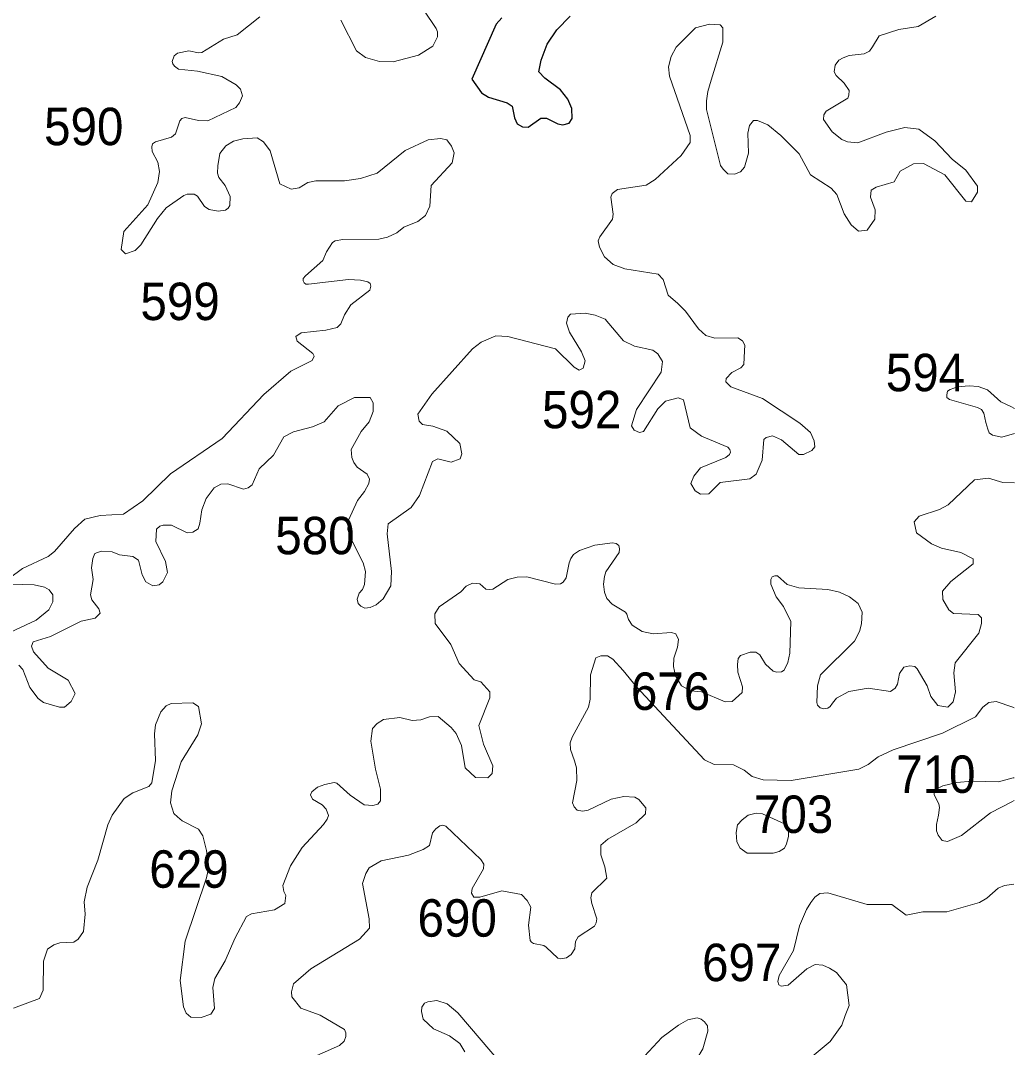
# Model space of a CAD drawing. Extents: x 499.9 to 555.3, y 9281.5 to 9336.8.
# Drawn here: x 551.055 to 555.305, y 9298.961 to 9303.351 of the extents above; entities that cross this region are included whole.
import ezdxf

# ---------------------------------------------------------------- set-up
doc = ezdxf.new("R2010")
doc.units = 0
doc.header["$LTSCALE"] = 0.064
doc.layers.add('1', color=7, linetype='Continuous', lineweight=25)
doc.layers.add('2', color=7, linetype='Continuous', lineweight=13)
doc.layers.add('21', color=7, linetype='Continuous')

msp = doc.modelspace()

# ---------------------------------------------------------------- linework, layer by layer
at = {"layer": '1'}
msp.add_lwpolyline([(553.1127, 9303.3619), (553.0892, 9303.3349), (552.9847, 9303.1), (553.0258, 9303.0418), (553.0556, 9303.023), (553.1358, 9302.9983), (553.157, 9302.9843), (553.1674, 9302.9346), (553.1789, 9302.9097), (553.2009, 9302.8966), (553.2251, 9302.8953), (553.2802, 9302.9335), (553.3035, 9302.9334), (553.3525, 9302.9085), (553.3743, 9302.9054), (553.4003, 9302.9116), (553.4136, 9302.9317), (553.4126, 9302.975), (553.3955, 9303.014), (553.3638, 9303.0545), (553.297, 9303.1037), (553.2717, 9303.1316), (553.2807, 9303.1811), (553.3073, 9303.2503), (553.3485, 9303.3108), (553.4057, 9303.3695)], dxfattribs=at)
at = {"layer": '2'}
for points in [[(552.4252, 9303.3521), (552.4919, 9303.2206), (552.5305, 9303.1932), (552.59, 9303.1751), (552.649, 9303.1742), (552.7564, 9303.2028), (552.8183, 9303.2409), (552.8376, 9303.281), (552.8381, 9303.3017), (552.8326, 9303.317), (552.7796, 9303.3945)], [(554.9685, 9303.3699), (554.8929, 9303.3257), (554.8109, 9303.312), (554.7269, 9303.285), (554.698, 9303.2378), (554.6844, 9303.2191), (554.6621, 9303.208), (554.5973, 9303.2017), (554.5726, 9303.1919), (554.5534, 9303.1812), (554.5374, 9303.1604), (554.5345, 9303.1311), (554.5427, 9303.1161), (554.5769, 9303.0831), (554.5973, 9303.0517), (554.5972, 9303.0309), (554.5927, 9303.0191), (554.4996, 9302.963), (554.4896, 9302.948), (554.4883, 9302.9281), (554.5256, 9302.8743), (554.5662, 9302.8415), (554.5907, 9302.8317), (554.6351, 9302.8273), (554.7555, 9302.8731), (554.8365, 9302.8935), (554.8954, 9302.8865), (554.9639, 9302.8365), (555.0382, 9302.7575), (555.0965, 9302.7116), (555.1468, 9302.6432), (555.1467, 9302.617), (555.1206, 9302.5755), (555.0967, 9302.5782), (555.0077, 9302.6904), (554.9153, 9302.7389), (554.8733, 9302.7376), (554.8166, 9302.7063), (554.7901, 9302.6617), (554.7134, 9302.6381), (554.6925, 9302.6251), (554.6887, 9302.5954), (554.7089, 9302.5411), (554.7071, 9302.5011), (554.6744, 9302.4551), (554.6378, 9302.4502), (554.6064, 9302.4769), (554.5772, 9302.5247), (554.5452, 9302.6072), (554.5217, 9302.634), (554.4331, 9302.691), (554.3841, 9302.7808), (554.3065, 9302.8587), (554.2509, 9302.9048), (554.2065, 9302.924), (554.1885, 9302.9233), (554.1713, 9302.9025), (554.1651, 9302.8691), (554.1681, 9302.7832), (554.1511, 9302.7233), (554.1327, 9302.7044), (554.1084, 9302.6943), (554.0795, 9302.6959)], [(552.8771, 9302.8409), (552.8503, 9302.8459), (552.7978, 9302.8411), (552.6992, 9302.7951), (552.5799, 9302.6986), (552.5081, 9302.6758), (552.4399, 9302.6656), (552.3172, 9302.6656), (552.2829, 9302.6583), (552.2471, 9302.6362), (552.2122, 9302.6299), (552.1637, 9302.6519), (552.1219, 9302.7934), (552.094, 9302.8315), (552.0673, 9302.8492), (552.0052, 9302.8445), (551.965, 9302.8343), (551.9325, 9302.8145), (551.9067, 9302.7822), (551.8981, 9302.7302), (551.8972, 9302.6981), (551.9028, 9302.6791), (551.9307, 9302.6448), (551.9509, 9302.5978), (551.9507, 9302.5598), (551.9436, 9302.5479), (551.9308, 9302.5394), (551.9008, 9302.5356), (551.8621, 9302.5424), (551.8423, 9302.5554), (551.8117, 9302.5996), (551.7972, 9302.6083), (551.7682, 9302.6084), (551.7531, 9302.6021), (551.6785, 9302.5495), (551.6403, 9302.5047), (551.5701, 9302.3924), (551.5452, 9302.3672), (551.5034, 9302.3528), (551.4854, 9302.3714), (551.4963, 9302.4495), (551.5988, 9302.5622), (551.642, 9302.6576), (551.65, 9302.706), (551.6426, 9302.7452), (551.6185, 9302.7913), (551.6171, 9302.8105), (551.6192, 9302.824), (551.6316, 9302.8324), (551.7001, 9302.8524), (551.7179, 9302.8666), (551.7363, 9302.9213), (551.7449, 9302.9312), (551.7591, 9302.9362), (551.8159, 9302.9227), (551.8564, 9302.9213), (551.9752, 9302.9791), (551.9912, 9302.9993), (552.0046, 9303.0293), (551.9958, 9303.057), (551.977, 9303.0763), (551.9161, 9303.1117), (551.8116, 9303.1335), (551.7309, 9303.1428), (551.7135, 9303.1559), (551.7066, 9303.1655), (551.7032, 9303.176), (551.7122, 9303.2003), (551.7261, 9303.2106), (551.7753, 9303.2215), (551.8154, 9303.2126), (551.8308, 9303.2143), (551.9225, 9303.2709), (551.9813, 9303.2897), (552.0779, 9303.366)], [(553.9937, 9303.0466), (554.0076, 9303.0951), (554.0578, 9303.2582), (554.0583, 9303.3196), (554.0459, 9303.3324), (554.0013, 9303.3345), (553.9412, 9303.3189), (553.859, 9303.2369), (553.8372, 9303.1962), (553.8262, 9303.1524), (553.8292, 9303.1128), (553.9178, 9302.8596), (553.9175, 9302.8289), (553.8794, 9302.7739), (553.7688, 9302.6707), (553.7296, 9302.6471), (553.6072, 9302.628), (553.5841, 9302.6113), (553.5791, 9302.595), (553.5892, 9302.5236), (553.5866, 9302.5018), (553.5316, 9302.4258), (553.5253, 9302.4094), (553.5301, 9302.3813), (553.5519, 9302.3407), (553.5895, 9302.3079), (553.6382, 9302.2891), (553.7818, 9302.2661), (553.8026, 9302.2436), (553.8238, 9302.176), (553.8658, 9302.1411), (553.898, 9302.1085), (553.9544, 9302.0332), (553.9847, 9302.0047), (554.0241, 9301.9932), (554.1225, 9301.9944), (554.1422, 9301.9818), (554.1516, 9301.9632), (554.1507, 9301.9389), (554.148, 9301.8805), (554.1341, 9301.8657), (554.096, 9301.8459), (554.0714, 9301.8209), (554.07, 9301.8067), (554.0922, 9301.7854), (554.227, 9301.7351), (554.3872, 9301.63), (554.432, 9301.5893), (554.4484, 9301.5536), (554.4511, 9301.5279), (554.4386, 9301.5124), (554.4028, 9301.4953), (554.3831, 9301.4951), (554.3081, 9301.5576), (554.2707, 9301.576), (554.2428, 9301.5685), (554.2335, 9301.5592), (554.2255, 9301.472), (554.2005, 9301.4115), (554.1727, 9301.3912), (554.0463, 9301.3755), (553.9976, 9301.328), (553.9623, 9301.3266), (553.9402, 9301.3397), (553.9217, 9301.3722), (553.9342, 9301.4025), (553.9618, 9301.4391), (554.0703, 9301.4834), (554.0859, 9301.4951), (554.0912, 9301.5056), (554.088, 9301.5172), (554.0798, 9301.5268), (553.966, 9301.5737), (553.9181, 9301.6103), (553.8893, 9301.7286), (553.8666, 9301.738), (553.8124, 9301.7241), (553.7793, 9301.6915), (553.7184, 9301.5944), (553.7011, 9301.5902), (553.6781, 9301.5993), (553.667, 9301.6178), (553.6893, 9301.6875), (553.7938, 9301.8477), (553.8, 9301.8931), (553.7806, 9301.9262), (553.7582, 9301.9421), (553.6796, 9301.9581), (553.6336, 9301.9809), (553.5542, 9302.0736), (553.5116, 9302.0913), (553.4687, 9302.0996), (553.4059, 9302.0961), (553.3946, 9302.0829), (553.39, 9302.0574)], [(554.0795, 9302.6959), (554.0597, 9302.7146), (554.0484, 9302.7314), (553.9883, 9302.971), (553.9887, 9303.0069), (553.9937, 9303.0466)], [(552.8055, 9302.5565), (552.8108, 9302.6455), (552.9003, 9302.742), (552.9089, 9302.7855), (552.8984, 9302.8143), (552.8771, 9302.8409)], [(551.0074, 9300.9675), (551.0631, 9301.0078), (551.1737, 9301.06), (551.2006, 9301.0807), (551.2855, 9301.1794), (551.3295, 9301.2197), (551.3952, 9301.2348), (551.4961, 9301.24), (551.5778, 9301.298), (551.6965, 9301.4136), (551.9169, 9301.5636), (552.096, 9301.7526), (552.2106, 9301.8513), (552.3021, 9301.8972), (552.3104, 9301.9166), (552.3046, 9301.9272), (552.2372, 9301.9795), (552.2322, 9301.9996), (552.2551, 9302.0151), (552.3602, 9302.0268), (552.4083, 9302.0381), (552.4251, 9302.0536), (552.4402, 9302.0923), (552.468, 9302.1355), (552.5485, 9302.1975), (552.5528, 9302.215), (552.5503, 9302.2264), (552.5399, 9302.2336), (552.5088, 9302.2411), (552.4578, 9302.243), (552.287, 9302.224), (552.2749, 9302.2242), (552.2682, 9302.2289), (552.2634, 9302.2376), (552.2642, 9302.2473), (552.2735, 9302.2596), (552.3483, 9302.3251), (552.3628, 9302.3622), (552.3883, 9302.4013), (552.4004, 9302.4093), (552.4325, 9302.4147), (552.5877, 9302.4164), (552.6242, 9302.424), (552.6641, 9302.4435), (552.6934, 9302.4674), (552.7542, 9302.4922), (552.7868, 9302.5172), (552.8055, 9302.5565)], [(553.39, 9302.0574), (553.4027, 9302.0186), (553.4538, 9301.935), (553.4687, 9301.896), (553.46, 9301.8649), (553.4436, 9301.8568)], [(553.4436, 9301.8568), (553.4218, 9301.869), (553.342, 9301.9474), (553.1392, 9302.0007), (553.088, 9302.0025), (553.0246, 9301.9758), (552.9875, 9301.947), (552.8134, 9301.7541), (552.7535, 9301.6684), (552.7602, 9301.6375), (552.7738, 9301.6234), (552.8176, 9301.6172), (552.878, 9301.5954), (552.9338, 9301.5433), (552.9421, 9301.4982), (552.9344, 9301.4776), (552.8965, 9301.4633), (552.8391, 9301.4771), (552.8167, 9301.4657), (552.7604, 9301.3199), (552.7252, 9301.2684), (552.6267, 9301.1992), (552.6231, 9301.1567), (552.6418, 9300.996), (552.6388, 9300.9346), (552.6051, 9300.879), (552.5755, 9300.8524), (552.5495, 9300.8409), (552.5272, 9300.8393), (552.5102, 9300.8466), (552.499, 9300.8592), (552.495, 9300.8775), (552.5034, 9300.9034), (552.5179, 9300.9179), (552.5257, 9300.9402), (552.5304, 9300.9953), (552.5207, 9301.0332), (552.4698, 9301.1305), (552.4541, 9301.1755), (552.4572, 9301.2156), (552.4955, 9301.2991), (552.5259, 9301.338), (552.5437, 9301.3721), (552.5473, 9301.3906), (552.5376, 9301.4115), (552.4949, 9301.442), (552.4797, 9301.4616), (552.4721, 9301.4831), (552.4686, 9301.5171), (552.5114, 9301.5935), (552.5461, 9301.6349), (552.5623, 9301.6797), (552.5635, 9301.716), (552.5498, 9301.7391), (552.4828, 9301.7388), (552.4133, 9301.7037), (552.3529, 9301.6346), (552.3037, 9301.614), (552.2217, 9301.5918), (552.1811, 9301.5715), (552.1372, 9301.4934), (552.0758, 9301.4348), (552.0449, 9301.3653), (552.0283, 9301.3531), (552.0079, 9301.3474), (551.9409, 9301.3701), (551.9112, 9301.3685), (551.8825, 9301.3532), (551.8491, 9301.308), (551.8297, 9301.2589), (551.8211, 9301.202), (551.8141, 9301.1775), (551.7918, 9301.1632), (551.7681, 9301.1604), (551.7012, 9301.1933), (551.6645, 9301.1934), (551.6502, 9301.1887), (551.6367, 9301.1766), (551.633, 9301.124), (551.6753, 9301.0388), (551.6834, 9300.9911), (551.6633, 9300.9513), (551.6485, 9300.938), (551.6208, 9300.9349), (551.5913, 9300.9515), (551.5758, 9300.9809), (551.5592, 9301.0442), (551.5346, 9301.0598), (551.4781, 9301.0665), (551.4463, 9301.0795), (551.3998, 9301.0825), (551.3732, 9301.0728), (551.3637, 9301.0516), (551.3592, 9301.0112), (551.3652, 9300.9617)], [(555.3046, 9301.5859), (555.25, 9301.5698), (555.2114, 9301.5777), (555.1967, 9301.5877), (555.1902, 9301.6039), (555.1823, 9301.6326), (555.174, 9301.6729), (555.1643, 9301.688), (555.146, 9301.6968), (555.0265, 9301.7311), (555.0154, 9301.7398), (555.0156, 9301.7503), (555.0187, 9301.7657), (555.03, 9301.7739), (555.0616, 9301.7844), (555.1111, 9301.7888), (555.1501, 9301.786), (555.1889, 9301.7727), (555.2463, 9301.7206), (555.2887, 9301.7002), (555.3047, 9301.6925)], [(554.3165, 9300.8463), (554.286, 9300.8869), (554.2625, 9300.9419), (554.2628, 9300.9618), (554.2693, 9300.9724), (554.2798, 9300.9767), (554.2921, 9300.977), (554.3324, 9300.9402), (554.3823, 9300.9253), (554.5069, 9300.9189), (554.5566, 9300.9067), (554.5994, 9300.8867), (554.6361, 9300.8593), (554.6531, 9300.8223), (554.6512, 9300.7715), (554.6426, 9300.7396), (554.6205, 9300.6983), (554.4751, 9300.5533), (554.4626, 9300.5065), (554.4597, 9300.435), (554.4627, 9300.4235), (554.4738, 9300.4133), (554.4903, 9300.4091), (554.5068, 9300.4115), (554.5167, 9300.4183), (554.5272, 9300.4329), (554.5445, 9300.4542), (554.5971, 9300.4828), (554.679, 9300.4968), (554.7751, 9300.4832), (554.7949, 9300.4972), (554.8046, 9300.5142), (554.8134, 9300.5594), (554.8315, 9300.586), (554.858, 9300.5922), (554.8787, 9300.5894), (554.8894, 9300.5799), (554.9309, 9300.5064), (554.9473, 9300.4606), (554.9773, 9300.4234), (555.0195, 9300.4162), (555.0431, 9300.4382), (555.053, 9300.481), (555.0452, 9300.562), (555.0517, 9300.605), (555.1528, 9300.7319), (555.1642, 9300.7731), (555.1644, 9300.7977), (555.1493, 9300.812), (555.0439, 9300.8162), (555.0241, 9300.8319), (554.9979, 9300.8751), (554.9976, 9300.912), (555.0324, 9300.9521), (555.1285, 9301.0276), (555.1281, 9301.05), (555.0754, 9301.0771), (554.9928, 9301.0949), (554.9495, 9301.1139), (554.8865, 9301.1602), (554.8765, 9301.2076), (554.8979, 9301.2324), (554.9846, 9301.2609), (555.0218, 9301.2805), (555.1335, 9301.3867), (555.194, 9301.3945), (555.2545, 9301.3757), (555.3044, 9301.3742)], [(552.5614, 9299.9958), (552.5828, 9300.0006), (552.5944, 9300.0157), (552.5938, 9300.0648), (552.5727, 9300.1501), (552.5529, 9300.2702), (552.5594, 9300.3249), (552.5801, 9300.3459), (552.6069, 9300.3631), (552.6767, 9300.3711), (552.7296, 9300.3586), (552.7667, 9300.3619), (552.8043, 9300.3742), (552.8414, 9300.3752), (552.8965, 9300.3282), (552.9171, 9300.3026), (552.9408, 9300.2518), (552.9562, 9300.1567), (553.001, 9300.1155), (553.0529, 9300.114), (553.0714, 9300.1317), (553.0744, 9300.1641), (553.0344, 9300.2568), (553.0145, 9300.3371), (553.0619, 9300.4555), (553.0618, 9300.4809), (553.0227, 9300.5233), (552.9952, 9300.5322), (552.9301, 9300.6021), (552.8942, 9300.6831), (552.8286, 9300.7732), (552.8266, 9300.8144), (552.8446, 9300.844), (552.9372, 9300.9087), (552.9603, 9300.9328), (552.9869, 9300.9453), (553.003, 9300.9449), (553.0189, 9300.9423), (553.0448, 9300.9206), (553.0585, 9300.9181), (553.0739, 9300.9205), (553.1385, 9300.9615), (553.179, 9300.9717), (553.2193, 9300.9728), (553.3424, 9300.941), (553.3639, 9300.9425), (553.3755, 9300.9501), (553.3875, 9300.9683), (553.4007, 9301.032), (553.4075, 9301.051), (553.4189, 9301.0681), (553.4456, 9301.0857), (553.5101, 9301.1079), (553.5864, 9301.1175), (553.6015, 9301.1147), (553.6125, 9301.1071), (553.6164, 9301.0923), (553.6153, 9301.0773), (553.5573, 9300.9947), (553.5525, 9300.9744), (553.5476, 9300.9414), (553.5523, 9300.9075), (553.5625, 9300.8799), (553.5842, 9300.8552), (553.6417, 9300.821), (553.6477, 9300.8134), (553.6547, 9300.791), (553.6708, 9300.7665), (553.7124, 9300.7393), (553.7598, 9300.7294), (553.8386, 9300.7341), (553.8575, 9300.7289), (553.8685, 9300.7046), (553.8638, 9300.6727), (553.8482, 9300.6257), (553.8467, 9300.59), (553.8558, 9300.5496), (553.8808, 9300.5063), (553.9208, 9300.4847), (553.9667, 9300.4806), (554.0673, 9300.4383), (554.0979, 9300.4391), (554.1411, 9300.4778), (554.1422, 9300.5031), (554.1221, 9300.5646), (554.1207, 9300.5973), (554.1238, 9300.6241), (554.134, 9300.6371), (554.1754, 9300.651), (554.1987, 9300.6505), (554.2166, 9300.6388), (554.2399, 9300.5989), (554.2726, 9300.5692), (554.2886, 9300.5655), (554.3089, 9300.5671)], [(551.3652, 9300.9617), (551.354, 9300.8954), (551.3606, 9300.8744), (551.3897, 9300.8364), (551.3955, 9300.818), (551.3743, 9300.7967)], [(550.9652, 9300.7152), (551.1217, 9300.7876), (551.1759, 9300.8312), (551.1933, 9300.8657), (551.1932, 9300.8962), (551.1781, 9300.9172), (551.1573, 9300.9292), (551.1139, 9300.9378), (551.0144, 9300.9411)], [(554.3089, 9300.5671), (554.3196, 9300.574), (554.3352, 9300.6061), (554.3448, 9300.6467), (554.3479, 9300.7819), (554.3165, 9300.8463)], [(551.3743, 9300.7967), (551.3137, 9300.783), (551.1836, 9300.7175), (551.109, 9300.6948), (551.1018, 9300.6765), (551.1113, 9300.6523), (551.1732, 9300.5825), (551.259, 9300.5311), (551.2884, 9300.4735), (551.2718, 9300.4404), (551.2429, 9300.4158), (551.2221, 9300.4159), (551.1532, 9300.4354), (551.131, 9300.453), (551.0954, 9300.4995), (551.0655, 9300.577), (551.0475, 9300.5949)], [(555.3035, 9300.413), (555.2973, 9300.4152), (555.2258, 9300.4403), (555.1951, 9300.4359), (555.1695, 9300.415), (555.1377, 9300.3747), (554.9966, 9300.3041), (554.7855, 9300.2326), (554.7223, 9300.2032), (554.679, 9300.1707), (554.6391, 9300.1511), (554.3505, 9300.1022), (554.2303, 9300.105), (554.1826, 9300.1199), (554.149, 9300.1466), (554.1036, 9300.1686), (554.0202, 9300.1709), (553.9798, 9300.1904), (553.6884, 9300.5026), (553.6311, 9300.5722), (553.5879, 9300.6204), (553.5649, 9300.6354), (553.5357, 9300.6351), (553.5155, 9300.6269), (553.4918, 9300.5542), (553.49, 9300.4492), (553.4838, 9300.415), (553.4134, 9300.288), (553.4057, 9300.2636), (553.4069, 9300.2347), (553.4241, 9300.1861), (553.4322, 9300.1562), (553.4343, 9300.1015), (553.4155, 9300.006), (553.4226, 9299.9889), (553.4347, 9299.9753), (553.4572, 9299.9716), (553.4814, 9299.975), (553.5801, 9300.0223), (553.6349, 9300.0341), (553.6811, 9300.0304), (553.6986, 9300.0209), (553.7287, 9299.9858), (553.7266, 9299.9603), (553.6874, 9299.9209), (553.5665, 9299.8516), (553.5367, 9299.825), (553.5365, 9299.7841), (553.5536, 9299.7336), (553.5615, 9299.685), (553.4984, 9299.6214), (553.4935, 9299.6001), (553.4983, 9299.5763), (553.5189, 9299.5109), (553.5164, 9299.4938), (553.5093, 9299.48), (553.4393, 9299.4336), (553.4283, 9299.4146), (553.4246, 9299.3829), (553.4089, 9299.3582), (553.3889, 9299.344), (553.3651, 9299.3404), (553.3523, 9299.3423), (553.3032, 9299.3894), (553.2925, 9299.3963), (553.2486, 9299.4052), (553.2403, 9299.4107), (553.234, 9299.4187), (553.2276, 9299.484), (553.2367, 9299.5611), (553.221, 9299.5896), (553.1966, 9299.6141), (553.1136, 9299.6311), (553.0182, 9299.6027), (552.9939, 9299.6041), (552.9828, 9299.6201), (552.9868, 9299.6407), (553.0341, 9299.725), (553.036, 9299.7447), (553.0232, 9299.7638), (552.8734, 9299.9063), (552.8586, 9299.9105), (552.8473, 9299.9077), (552.8309, 9299.8962), (552.8169, 9299.8786), (552.8038, 9299.8238), (552.7762, 9299.8065), (552.7135, 9299.7828), (552.5973, 9299.7583), (552.5464, 9299.7281), (552.5318, 9299.7052), (552.5178, 9299.6612), (552.5462, 9299.5101), (552.5471, 9299.4715), (552.5042, 9299.4239)], [(551.0246, 9299.1291), (551.1356, 9299.1696), (551.1521, 9299.2055), (551.1537, 9299.3302), (551.1711, 9299.3805), (551.1977, 9299.3998), (551.2238, 9299.4079), (551.2832, 9299.4104), (551.3015, 9299.4241), (551.3241, 9299.4571), (551.3319, 9299.5307), (551.3273, 9299.5841), (551.3398, 9299.6463), (551.386, 9299.7616), (551.4285, 9299.9127), (551.4469, 9299.9533), (551.4976, 9300.0252), (551.5351, 9300.0493), (551.6033, 9300.0766), (551.6171, 9300.0925), (551.6327, 9300.1882), (551.628, 9300.301), (551.6327, 9300.3402), (551.6549, 9300.3959), (551.6781, 9300.4208), (551.6987, 9300.4317), (551.7925, 9300.4343), (551.8167, 9300.4186), (551.8283, 9300.3443), (551.8128, 9300.2972), (551.7424, 9300.1826), (551.7014, 9300.0584), (551.6965, 9300.0065), (551.7106, 9299.9606), (551.7259, 9299.9474), (551.7458, 9299.9304), (551.8158, 9299.8945), (551.8342, 9299.8655), (551.8509, 9299.8031), (551.8606, 9299.7327), (551.8506, 9299.686), (551.7589, 9299.4154), (551.7379, 9299.2473), (551.7516, 9299.1346), (551.763, 9299.1069), (551.7827, 9299.0903), (551.8276, 9299.0888), (551.8683, 9299.1032), (551.8842, 9299.1278), (551.878, 9299.2173), (551.886, 9299.2555), (551.9307, 9299.3311), (551.9715, 9299.4267), (552.0216, 9299.5211), (552.0425, 9299.5324), (552.1413, 9299.5498), (552.1856, 9299.5762), (552.1896, 9299.6112), (552.1803, 9299.6271), (552.1773, 9299.6534), (552.2093, 9299.7369), (552.2587, 9299.8163), (552.3501, 9299.9136), (552.3655, 9299.9362), (552.3719, 9299.9527), (552.3615, 9299.9801), (552.3451, 9299.9976), (552.3033, 9300.0222), (552.2953, 9300.0411), (552.301, 9300.0538), (552.3243, 9300.0737), (552.3562, 9300.0849)], [(552.3562, 9300.0849), (552.3954, 9300.0938), (552.408, 9300.091), (552.4642, 9300.0397), (552.5242, 9299.9974), (552.5614, 9299.9958)], [(555.3031, 9300.0162), (555.2928, 9300.0109), (555.2018, 9299.9636), (555.0785, 9299.8677), (555.0183, 9299.842), (554.9951, 9299.8459), (554.9782, 9299.8684), (554.972, 9299.8867), (554.9712, 9299.9139), (554.9799, 9299.9545), (554.9845, 9299.9861), (554.9818, 9300.0025), (554.9615, 9300.0404), (554.9609, 9300.0554), (554.9683, 9300.0652), (554.9982, 9300.0796), (555.0577, 9300.094), (555.123, 9300.0992), (555.2362, 9300.0966), (555.2988, 9300.1131), (555.3032, 9300.1142)], [(554.4307, 9298.915), (554.5166, 9298.9866), (554.5665, 9299.0566), (554.5807, 9299.097), (554.5978, 9299.1402), (554.5867, 9299.2293), (554.5433, 9299.2814), (554.5138, 9299.3003), (554.485, 9299.3125), (554.4533, 9299.3161), (554.4167, 9299.2974), (554.3374, 9299.2279), (554.3076, 9299.2223), (554.2974, 9299.2287), (554.2923, 9299.2423), (554.2992, 9299.2684), (554.3604, 9299.3759), (554.3854, 9299.4813), (554.4149, 9299.551), (554.4345, 9299.5808), (554.4512, 9299.6028), (554.4728, 9299.6191), (554.5071, 9299.6214), (554.6751, 9299.5725), (554.7808, 9299.572), (554.8415, 9299.5264), (554.9131, 9299.5405), (555.0157, 9299.5404), (555.1549, 9299.5811), (555.1867, 9299.5993), (555.2344, 9299.6413), (555.2616, 9299.6533), (555.3027, 9299.6596)], [(552.5042, 9299.4239), (552.2969, 9299.2975), (552.2224, 9299.2335), (552.2139, 9299.199), (552.2157, 9299.177), (552.2532, 9299.1288)], [(553.1151, 9298.8858), (552.9246, 9299.1092), (552.8788, 9299.1475), (552.8353, 9299.1616), (552.7972, 9299.1563), (552.7821, 9299.1496), (552.771, 9299.1336), (552.7696, 9299.1144), (552.7762, 9299.0816), (552.8203, 9299.0408), (552.8885, 9299.0104), (552.9334, 9298.9777), (552.9545, 9298.9421)], [(552.2532, 9299.1288), (552.3369, 9299.0991), (552.4408, 9299.0372), (552.4461, 9299.0229), (552.4457, 9299.0083), (552.4386, 9298.9884), (552.4189, 9298.9698), (552.1225, 9298.8383)], [(553.993, 9299.0302), (553.9921, 9299.0541), (553.9788, 9299.0699), (553.9653, 9299.0823), (553.9476, 9299.0878), (553.908, 9299.0784), (553.8676, 9299.0561), (553.7968, 9299.0035), (553.7042, 9298.9035)], [(553.7799, 9298.6967), (553.7729, 9298.7064), (553.8155, 9298.7764), (553.9457, 9298.9101), (553.9729, 9298.9548), (553.993, 9299.0302)]]:
    msp.add_lwpolyline(points, dxfattribs=at)
msp.add_lwpolyline([(554.2993, 9299.7992), (554.3213, 9299.8123), (554.3303, 9299.8315), (554.3386, 9299.8625), (554.339, 9299.8892), (554.3213, 9299.9169), (554.2277, 9299.9589), (554.2008, 9299.9624), (554.166, 9299.954), (554.1399, 9299.9341), (554.1209, 9299.9128), (554.1147, 9299.8797), (554.1175, 9299.8398), (554.1323, 9299.813), (554.1615, 9299.7908), (554.2731, 9299.7909)], close=True, dxfattribs=at)

# ---------------------------------------------------------------- texts
at = {"layer": '21', "width": 0.95}
for s, p in [('590', (551.1559, 9302.8178)), ('599', (551.5678, 9302.0702)), ('594', (554.7547, 9301.7661)), ('592', (553.2848, 9301.6077)), ('580', (552.1443, 9301.0692)), ('676', (553.6649, 9300.4039)), ('710', (554.799, 9300.0491)), ('703', (554.1908, 9299.878)), ('629', (551.6058, 9299.6436)), ('690', (552.7526, 9299.4345)), ('697', (553.969, 9299.2444))]:
    msp.add_text(s, height=0.16, dxfattribs=at).set_placement(p)

doc.saveas('drawing.dxf')
